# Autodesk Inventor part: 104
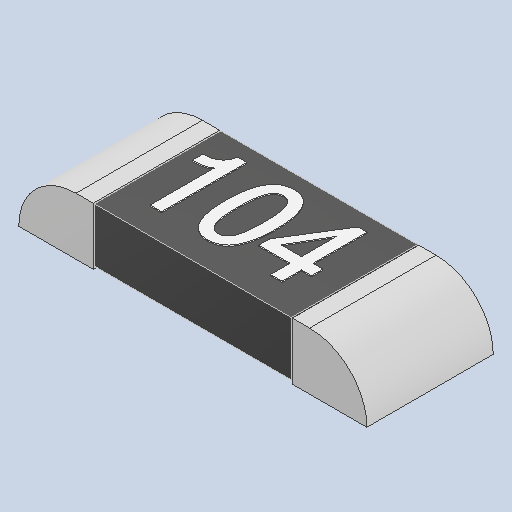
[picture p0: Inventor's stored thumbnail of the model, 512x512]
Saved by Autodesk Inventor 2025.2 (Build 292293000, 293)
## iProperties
Created: 2025-04
Part Number: 104
Material: Generic
Description: PART-104-DESC
Document SubType Name: Modeling
Designer: BennF
Density: 1 g/cm^3
Appearance: Default
Author: BennF
Revision Number: NONE
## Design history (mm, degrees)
feature "Solid"
feature "pin"
feature "1"
feature "0"
feature "4"
body "Solid1"
body "Solid2"
body "Solid3"
body "Solid4"
body "Solid5"
